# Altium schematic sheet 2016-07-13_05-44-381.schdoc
size 307 x 144 mm; SheetNumber: 1; SheetTotal: 1
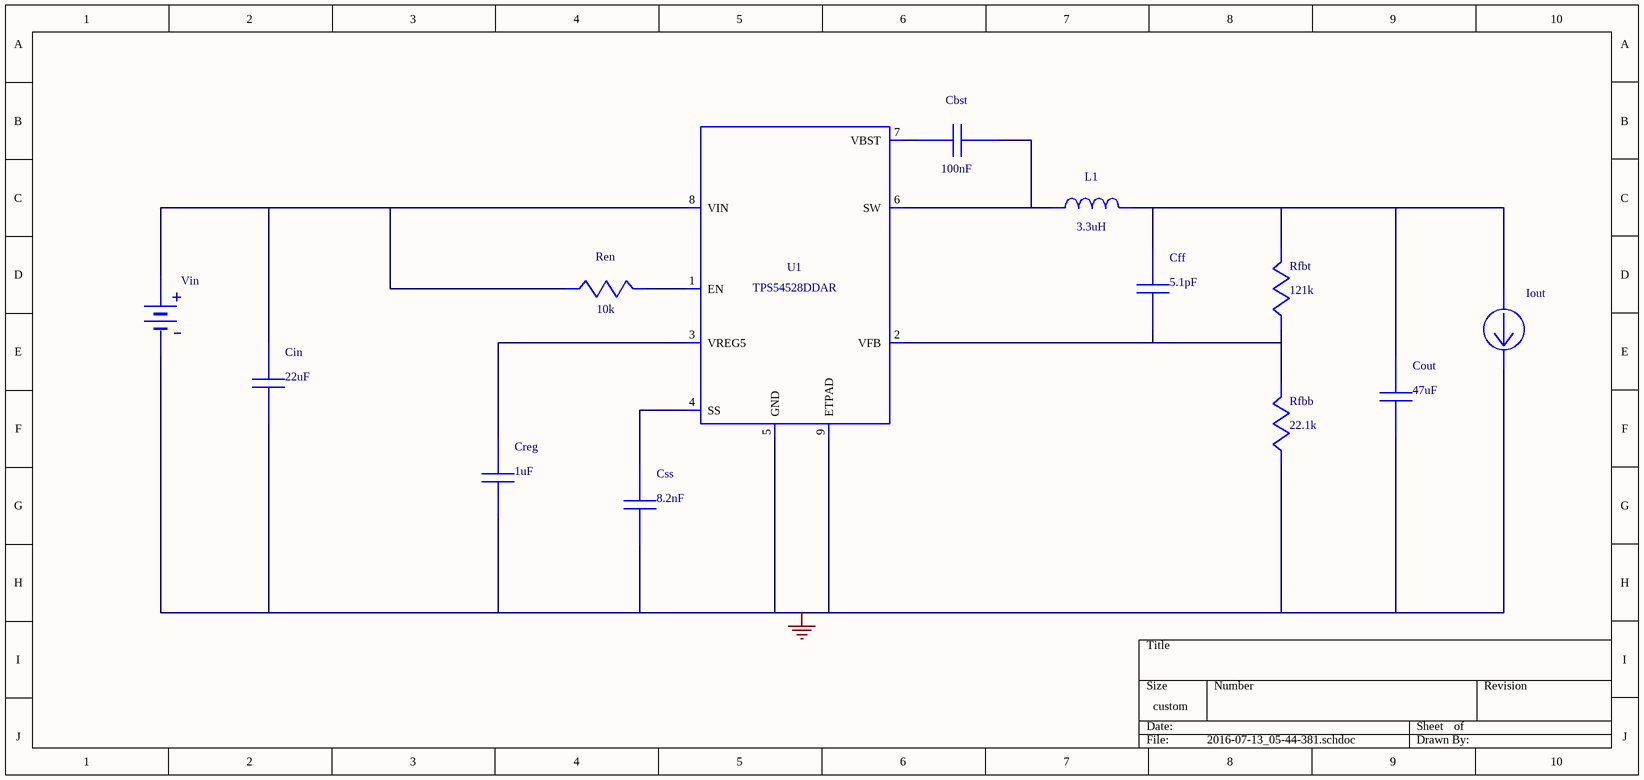
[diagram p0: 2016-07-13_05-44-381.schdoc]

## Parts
Cbst  value 100nF  (hidden comment: GRM155R61A104KA01D)
Cff  value 5.1pF  (hidden comment: GRM1555C1E5R1CA01D)
Cin  value 22uF  (hidden comment: GRM32ER61E226KE15L)
Cout  value 47uF  (hidden comment: GRM31CR61A476KE15L)
Creg  value 1uF  (hidden comment: GRM188R61A105KA61D)
Css  value 8.2nF  (hidden comment: GRM033R61A822KA01D)
Iout  WB_CURRENT_LOAD  (value not drawn)
L1  value 3.3uH  (hidden comment: SRN6045-3R3Y)
Ren  value 10k  (hidden comment: CRCW040210K0FKED)
Rfbb  value 22.1k  (hidden comment: CRCW040222K1FKED)
Rfbt  value 121k  (hidden comment: CRCW0402121KFKED)
U1  TPS54528DDAR
Vin  WB_BATTERY  (value not drawn)

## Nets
0: Cin.2 Cout.2 Creg.2 Css.2 Iout.2(-) Rfbb.2 U1.5(GND) U1.9(ETPAD) Vin.2(-)
NetCbst_1: Cbst.1 U1.7(VBST)
NetCbst_2: Cbst.2 L1.1 U1.6(SW)
NetCff_1: Cff.1 Cout.1 Iout.1(+) L1.2 Rfbt.1
NetCff_2: Cff.2 Rfbb.1 Rfbt.2 U1.2(VFB)
NetCin_1: Cin.1 Ren.2 U1.8(VIN) Vin.1(+)
NetCreg_1: Creg.1 U1.3(VREG5)
NetCss_1: Css.1 U1.4(SS)
NetRen_1: Ren.1 U1.1(EN)

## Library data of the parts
Cbst = GRM155R61A104KA01D: GRM155R61A104KA0; Manufacturer Name: MuRata
Cff = GRM1555C1E5R1CA01D: GRM1555C1E5R1CA0; Manufacturer Name: MuRata
Cin = GRM32ER61E226KE15L: GRM32ER61E226KE1; Manufacturer Name: MuRata
Cout = GRM31CR61A476KE15L: GRM31CR61A476KE1; Manufacturer Name: MuRata
Creg = GRM188R61A105KA61D: GRM188R61A105KA6; Manufacturer Name: MuRata
Css = GRM033R61A822KA01D: GRM033R61A822KA0; Manufacturer Name: MuRata
L1 = SRN6045-3R3Y: Manufacturer Name: Bourns
Ren = CRCW040210K0FKED: Manufacturer Name: Vishay-Dale
Rfbb = CRCW040222K1FKED: Manufacturer Name: Vishay-Dale
Rfbt = CRCW0402121KFKED: Manufacturer Name: Vishay-Dale
U1 = TPS54528DDAR: Manufacturer Name: Texas Instruments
